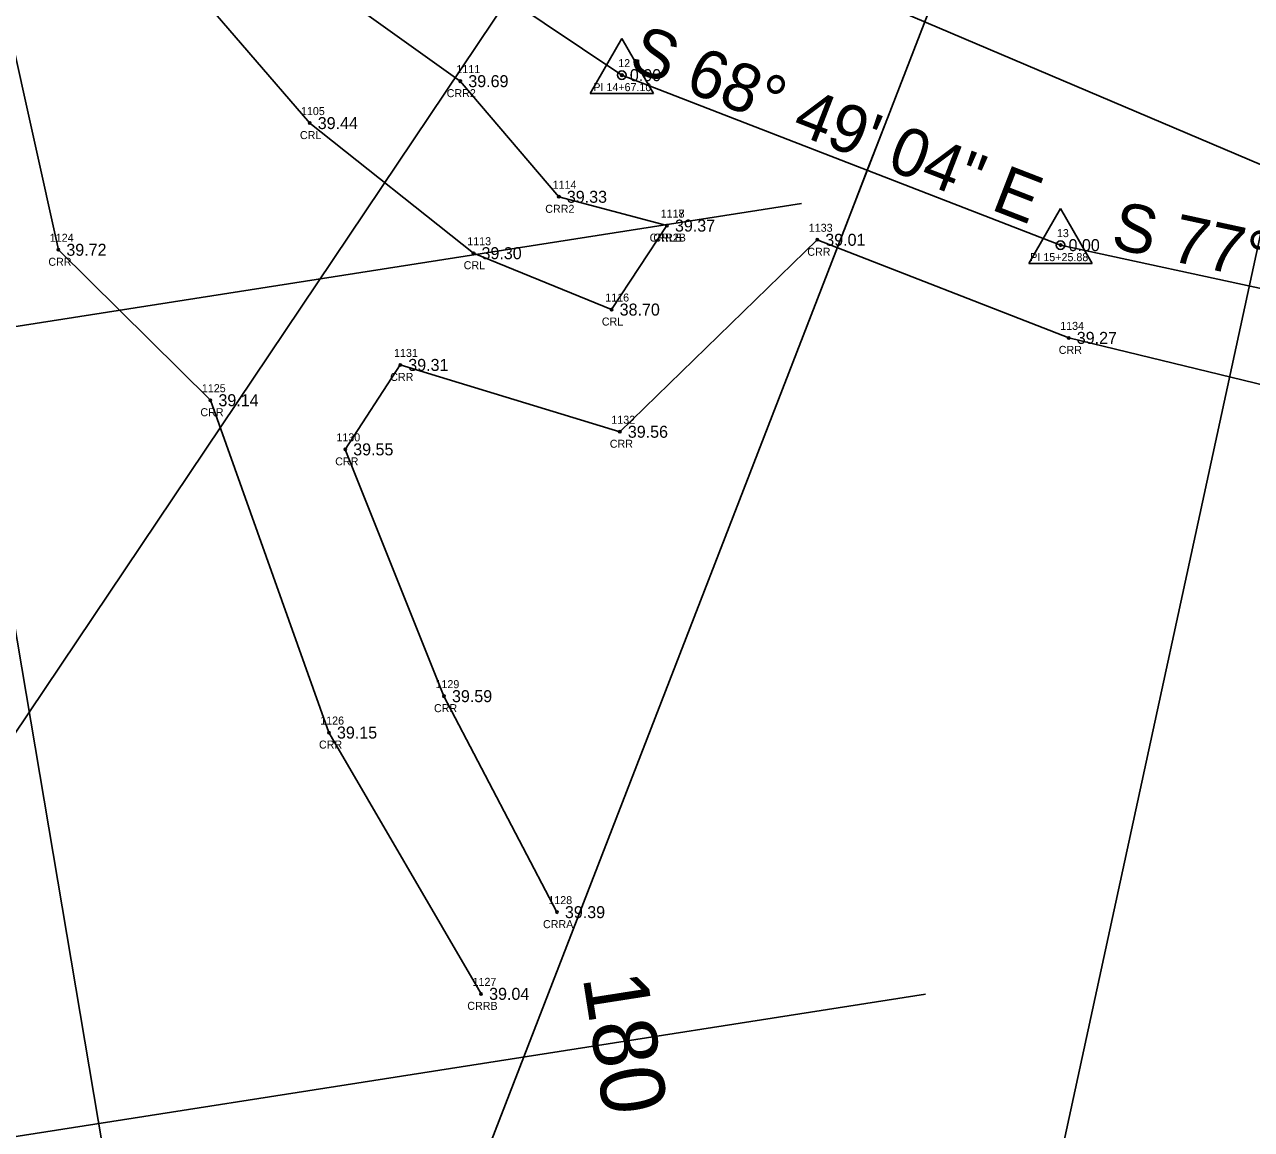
# Model space of a CAD drawing. Extents: x 2619568 to 2620316, y 784340 to 785138.
# Drawn here: x 2619906.4 to 2620059.7, y 784608.4 to 784746.5 of the extents above; entities that cross this region are included whole.
import ezdxf

# ---------------------------------------------------------------- set-up
doc = ezdxf.new("R2010")
doc.units = 0
for name, color, linetype in [('RD_EX_H2O', 7, 'Continuous'), ('RD_EX_H2O_txCode', 7, 'Continuous'), ('RD_EX_TX_H2O_ELEV', 7, 'Continuous'), ('RD_EX_VEG', 7, 'Continuous'), ('RD_HC_Cl', 7, 'Continuous'), ('RD_HC_Data', 7, 'Continuous'), ('RD_HC_Data_Tic', 7, 'Continuous'), ('RD_HC_Survey_ELEV', 7, 'Continuous'), ('RD_HC_TX_Sta50', 7, 'Continuous'), ('RD_HC_txCode', 7, 'Continuous'), ('RD_PD_PatLn1', 7, 'Continuous'), ('RD_PD_PatLn2', 7, 'Continuous'), ('RD_SMD_Locator', 7, 'Continuous')]:
    doc.layers.add(name, color=color, linetype=linetype)

msp = doc.modelspace()

# ---------------------------------------------------------------- linework, layer by layer
at = {"layer": 'RD_EX_H2O'}
for points in [[(2619931.64, 784808.99), (2619931.64, 784784.57), (2619938.44, 784774.64), (2619973.07, 784754.13), (2619998.87, 784755.37), (2620062.51, 784728.27), (2620105.87, 784718.88)], [(2619858.79, 784802.44), (2619861.97, 784802.62), (2619885.46, 784800.96), (2619898.93, 784793.37), (2619901.36, 784760.21), (2619910.66, 784718.33), (2619929.66, 784699.53), (2619944.47, 784658), (2619963.48, 784625.35)], [(2619911.58, 784769.51), (2619915.23, 784772.04), (2619960.88, 784739.4), (2619973.19, 784724.95), (2619986.7, 784721.35)], [(2619911.58, 784769.51), (2619942.07, 784734.16), (2619962.53, 784717.9), (2619979.79, 784710.86), (2619986.7, 784721.35)], [(2619972.95, 784635.56), (2619958.84, 784662.55), (2619946.5, 784693.39), (2619953.38, 784703.94), (2619980.81, 784695.59), (2620005.48, 784719.58), (2620036.9, 784707.32), (2620099.35, 784692.16)]]:
    msp.add_lwpolyline(points, dxfattribs=at)
at = {"layer": 'RD_EX_VEG'}
msp.add_lwpolyline([(2619930.82, 784519.47), (2619827.3, 785132.88)], dxfattribs=at)
at = {"layer": 'RD_HC_Cl'}
for p, q in [((2619923.2, 784779.01), (2619981.06, 784740.15)), ((2619981.06, 784740.15), (2620035.87, 784718.91)), ((2620035.87, 784718.91), (2620104.35, 784704.08))]:
    msp.add_line(p, q, dxfattribs=at)
at = {"layer": 'RD_HC_Data'}
for p, q in [((2619977.09, 784737.86), (2619981.06, 784744.74)), ((2619981.06, 784744.74), (2619985.03, 784737.86)), ((2619977.09, 784737.86), (2619985.03, 784737.86)), ((2620031.9, 784716.62), (2620035.87, 784723.5)), ((2620035.87, 784723.5), (2620039.84, 784716.62)), ((2620031.9, 784716.62), (2620039.84, 784716.62))]:
    msp.add_line(p, q, dxfattribs=at)
for centre in [(2619981.06, 784740.15), (2620035.87, 784718.91)]:
    msp.add_circle(centre, 0.529, dxfattribs=at)
at = {"layer": 'RD_HC_Data_Tic'}
for q in [(2620014.62, 784735.72), (2620008.84, 784720.8)]:
    msp.add_line((2620011.73, 784728.26), q, dxfattribs=at)
at = {"layer": 'RD_PD_PatLn1'}
for p, q in [((2620003.52, 784724.12), (2619707.14, 784677.65)), ((2620019.01, 784625.33), (2619722.63, 784578.86))]:
    msp.add_line(p, q, dxfattribs=at)
at = {"layer": 'RD_PD_PatLn2'}
for p, q in [((2620050.49, 784874.21), (2619883.23, 784625.16)), ((2620065.93, 784868.13), (2619957.53, 784588.4)), ((2620091.2, 784860.41), (2620027.68, 784567.21))]:
    msp.add_line(p, q, dxfattribs=at)
at = {"layer": 'RD_SMD_Locator'}
for centre in [(2619960.88, 784739.4), (2619981.06, 784740.15), (2619942.07, 784734.16), (2619973.19, 784724.95), (2619986.7, 784721.35), (2619986.7, 784721.35), (2620005.48, 784719.58), (2620035.87, 784718.91), (2619910.66, 784718.33), (2619962.53, 784717.9), (2619979.79, 784710.86), (2620036.9, 784707.32), (2619953.38, 784703.94), (2619929.66, 784699.53), (2619980.81, 784695.59), (2619946.5, 784693.39), (2619958.84, 784662.55), (2619944.47, 784658), (2619972.95, 784635.56), (2619963.48, 784625.35)]:
    msp.add_circle(centre, 0.15, dxfattribs=at)

# ---------------------------------------------------------------- texts
at = {"layer": 'RD_EX_H2O_txCode'}
for s, p in [('1111', (2619960.39, 784740.4)), ('CRR2', (2619959.18, 784737.4)), ('1105', (2619940.97, 784735.16)), ('CRL', (2619940.84, 784732.16)), ('1114', (2619972.41, 784725.95)), ('CRR2', (2619971.49, 784722.95)), ('1118', (2619985.92, 784722.35)), ('1117', (2619985.92, 784722.35)), ('1133', (2620004.42, 784720.58)), ('1124', (2619909.59, 784719.33)), ('1113', (2619961.75, 784718.9)), ('CRR2B', (2619984.53, 784719.35)), ('CRLB', (2619985, 784719.35)), ('CRR', (2619909.41, 784716.33)), ('CRR', (2620004.23, 784717.58)), ('CRL', (2619961.3, 784715.9)), ('1116', (2619978.99, 784711.86)), ('CRL', (2619978.56, 784708.86)), ('1134', (2620035.83, 784708.32)), ('1131', (2619952.6, 784704.94)), ('CRR', (2620035.65, 784705.32)), ('CRR', (2619952.12, 784701.94)), ('1125', (2619928.59, 784700.53)), ('CRR', (2619928.41, 784697.53)), ('1132', (2619979.75, 784696.59)), ('1130', (2619945.4, 784694.39)), ('CRR', (2619979.56, 784693.59)), ('CRR', (2619945.25, 784691.39)), ('1129', (2619957.78, 784663.55)), ('CRR', (2619957.59, 784660.55)), ('1126', (2619943.38, 784659)), ('CRR', (2619943.22, 784656)), ('1128', (2619971.88, 784636.56)), ('CRRA', (2619971.21, 784633.56)), ('1127', (2619962.41, 784626.35)), ('CRRB', (2619961.75, 784623.35))]:
    msp.add_text(s, height=1, dxfattribs=at).set_placement(p)
at = {"layer": 'RD_EX_TX_H2O_ELEV'}
for s, p in [('39.69', (2619961.88, 784738.65)), ('39.44', (2619943.07, 784733.41)), ('39.33', (2619974.19, 784724.2)), ('39.37', (2619987.7, 784720.6)), ('39.37', (2619987.7, 784720.6)), ('39.72', (2619911.66, 784717.58)), ('39.01', (2620006.48, 784718.83)), ('39.30', (2619963.53, 784717.15)), ('38.70', (2619980.79, 784710.11)), ('39.27', (2620037.9, 784706.57)), ('39.31', (2619954.38, 784703.19)), ('39.14', (2619930.66, 784698.78)), ('39.56', (2619981.81, 784694.84)), ('39.55', (2619947.5, 784692.64)), ('39.59', (2619959.84, 784661.8)), ('39.15', (2619945.47, 784657.25)), ('39.39', (2619973.95, 784634.81)), ('39.04', (2619964.48, 784624.6))]:
    msp.add_text(s, height=1.5, dxfattribs=at).set_placement(p)
at = {"layer": 'RD_HC_Data'}
for s, rotation, p in [('S 68%%d 49\' 04" E', 338.8179, (2619981.67, 784740.99)), ('S 77%%d 46\' 36" E', 347.7766, (2620041.99, 784718.61))]:
    msp.add_text(s, height=6, rotation=rotation, dxfattribs=at).set_placement(p)
at = {"layer": 'RD_HC_Survey_ELEV'}
for p in [(2619982.06, 784739.4), (2620036.87, 784718.16)]:
    msp.add_text('0.00', height=1.5, dxfattribs=at).set_placement(p)
at = {"layer": 'RD_HC_TX_Sta50'}
msp.add_text('180', height=8, rotation=278.9109, dxfattribs=at).set_placement((2619976.16, 784627.45))
at = {"layer": 'RD_HC_txCode'}
for s, p in [('12', (2619980.61, 784741.15)), ('PI 14+67.10', (2619977.5, 784738.15)), ('13', (2620035.42, 784719.91)), ('PI 15+25.88', (2620032.09, 784716.91))]:
    msp.add_text(s, height=1, dxfattribs=at).set_placement(p)

doc.saveas('drawing.dxf')
